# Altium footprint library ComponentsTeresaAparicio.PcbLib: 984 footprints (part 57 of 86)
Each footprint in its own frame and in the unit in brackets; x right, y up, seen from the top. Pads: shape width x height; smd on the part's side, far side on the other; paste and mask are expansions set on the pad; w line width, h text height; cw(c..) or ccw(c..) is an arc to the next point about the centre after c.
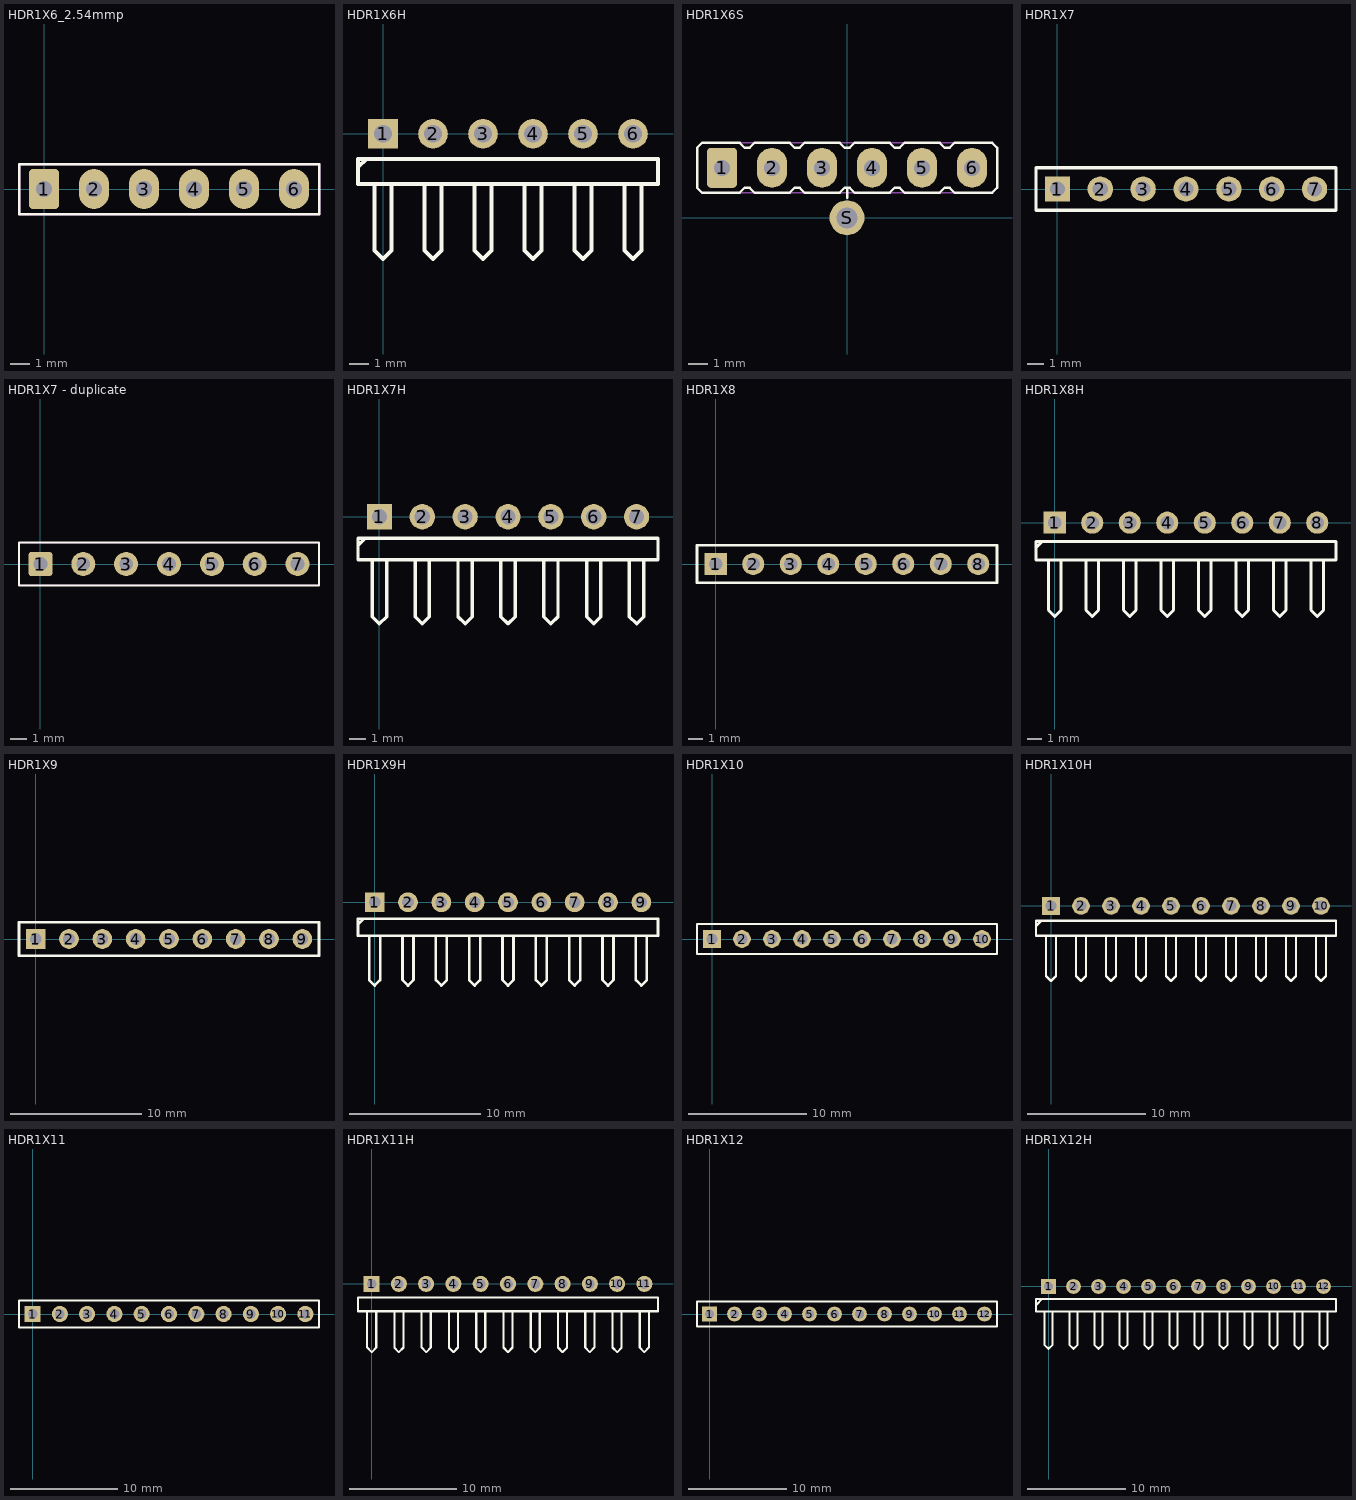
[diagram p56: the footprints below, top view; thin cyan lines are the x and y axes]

## HDR1X6_2.54mmp [mil] "Connector; Header; 6 Position 0.100\" pitch"
pads (6):
  rrect25% 60x80 hole 32: 1(0,0)
  oval 60x80 hole 32: 2(100,0) 3(200,0) 4(300,0) 5(400,0) 6(500,0)
Top Overlay:
  lines w5: -50,-50 -50,50 550,50 550,-50 -50,-50
Mechanical 13:
  lines w5: -50,-50 550,-50 550,50 -50,50 -50,-50

## HDR1X6H [mm] "Connector; Header; 6 Position; Right Angle"
pads (6):
  rect 1.5x1.5 hole 0.9: 1(0,0)
  round 1.5 hole 0.9: 2(2.54,0) 3(5.08,0) 4(7.62,0) 5(10.16,0) 6(12.7,0)
Top Overlay:
  lines w0.2: -1.27,-1.693 -0.847,-1.27 ; -0.423,-2.54 -0.423,-5.927 0,-6.35 0.423,-5.927 0.423,-2.54 ; 2.117,-2.54 2.117,-5.927 2.54,-6.35 2.963,-5.927 2.963,-2.54 ; 4.657,-2.54 4.657,-5.927 5.08,-6.35 5.503,-5.927 5.503,-2.54 ; 7.197,-2.54 7.197,-5.927 7.62,-6.35 8.043,-5.927 8.043,-2.54 ; 9.737,-2.54 9.737,-5.927 10.16,-6.35 10.583,-5.927 10.583,-2.54 ; 12.277,-2.54 12.277,-5.927 12.7,-6.35 13.123,-5.927 13.123,-2.54 ; -1.27,-2.54 -1.27,-1.27 13.97,-1.27 13.97,-2.54 -1.27,-2.54

## HDR1X6S [mil] "Connector; Special 6-position header with shield term"
pads (7):
  rrect25% 60x80 hole 32: 1(-250,100)
  oval 60x80 hole 32: 2(-150,100) 3(-50,100) 4(50,100) 5(150,100) 6(250,100)
  round 70 hole 42: S(0,0)
Top Overlay:
  lines w5: 0,40 0,60 ; -300,60 -300,140 -290,150 -215,150 -205,140 -195,140 -185,150 -115,150 -105,140 -95,140 -85,150 -15,150 -5,140 5,140 15,150 85,150 95,140 105,140 115,150 185,150 195,140 205,140 215,150 290,150 300,140 300,60 290,50 215,50 205,60 195,60 185,50 115,50 105,60 95,60 85,50 15,50 5,60 -5,60 -15,50 -85,50 -95,60 -105,60 -115,50 -185,50 -195,60 -205,60 -215,50 -290,50 -300,60
Mechanical 13:
  lines w3: -300,60 -290,50 290,50 300,60 300,140 290,150 -290,150 -300,140 -300,60

## HDR1X7 [mm] "Connector; Header; 7 Position"
pads (7):
  rect 1.5x1.5 hole 0.9: 1(0,0)
  round 1.5 hole 0.9: 2(2.54,0) 3(5.08,0) 4(7.62,0) 5(10.16,0) 6(12.7,0) 7(15.24,0)
Top Overlay:
  lines w0.2: -1.27,-1.27 -1.27,1.27 16.51,1.27 16.51,-1.27 -1.27,-1.27

## HDR1X7 - duplicate [mil] "Connector; Header; 7 Position"
pads (7):
  rrect25% 56x56 / inner rrect25% 56x56 / far side rrect25% 72x72 hole 32: 1(0,0)
  round 56 / inner round 56 / far side round 72 hole 32: 2(100,0) 3(200,0) 4(300,0) 5(400,0) 6(500,0) 7(600,0)
Top Overlay:
  lines w5: -50,-50 650,-50 650,50 -50,50 -50,-50
Mechanical 13:
  lines w3: -50,-50 -50,50 650,50 650,-50 -50,-50

## HDR1X7H [mm] "Connector; Header; 7 Position; Right Angle"
pads (7):
  rect 1.5x1.5 hole 0.9: 1(0,0)
  round 1.5 hole 0.9: 2(2.54,0) 3(5.08,0) 4(7.62,0) 5(10.16,0) 6(12.7,0) 7(15.24,0)
Top Overlay:
  lines w0.2: -1.27,-1.693 -0.847,-1.27 ; -0.423,-2.54 -0.423,-5.927 0,-6.35 0.423,-5.927 0.423,-2.54 ; 2.117,-2.54 2.117,-5.927 2.54,-6.35 2.963,-5.927 2.963,-2.54 ; 4.657,-2.54 4.657,-5.927 5.08,-6.35 5.503,-5.927 5.503,-2.54 ; 7.197,-2.54 7.197,-5.927 7.62,-6.35 8.043,-5.927 8.043,-2.54 ; 9.737,-2.54 9.737,-5.927 10.16,-6.35 10.583,-5.927 10.583,-2.54 ; 12.277,-2.54 12.277,-5.927 12.7,-6.35 13.123,-5.927 13.123,-2.54 ; 14.817,-2.54 14.817,-5.927 15.24,-6.35 15.663,-5.927 15.663,-2.54 ; -1.27,-2.54 -1.27,-1.27 16.51,-1.27 16.51,-2.54 -1.27,-2.54

## HDR1X8 [mm] "Connector; Header; 8 Position"
pads (8):
  rect 1.5x1.5 hole 0.9: 1(0,0)
  round 1.5 hole 0.9: 2(2.54,0) 3(5.08,0) 4(7.62,0) 5(10.16,0) 6(12.7,0) 7(15.24,0) 8(17.78,0)
Top Overlay:
  lines w0.2: -1.27,-1.27 19.05,-1.27 19.05,1.27 -1.27,1.27 -1.27,-1.27

## HDR1X8H [mm] "Connector; Header; 8 Position; Right Angle"
pads (8):
  rect 1.5x1.5 hole 0.9: 1(0,0)
  round 1.5 hole 0.9: 2(2.54,0) 3(5.08,0) 4(7.62,0) 5(10.16,0) 6(12.7,0) 7(15.24,0) 8(17.78,0)
Top Overlay:
  lines w0.2: -1.27,-1.693 -0.847,-1.27 ; -0.423,-2.54 -0.423,-5.927 0,-6.35 0.423,-5.927 0.423,-2.54 ; 2.117,-2.54 2.117,-5.927 2.54,-6.35 2.963,-5.927 2.963,-2.54 ; 4.657,-2.54 4.657,-5.927 5.08,-6.35 5.503,-5.927 5.503,-2.54 ; 7.197,-2.54 7.197,-5.927 7.62,-6.35 8.043,-5.927 8.043,-2.54 ; 9.737,-2.54 9.737,-5.927 10.16,-6.35 10.583,-5.927 10.583,-2.54 ; 12.277,-2.54 12.277,-5.927 12.7,-6.35 13.123,-5.927 13.123,-2.54 ; 14.817,-2.54 14.817,-5.927 15.24,-6.35 15.663,-5.927 15.663,-2.54 ; 17.357,-2.54 17.357,-5.927 17.78,-6.35 18.203,-5.927 18.203,-2.54 ; -1.27,-2.54 -1.27,-1.27 19.05,-1.27 19.05,-2.54 -1.27,-2.54

## HDR1X9 [mm] "Connector; Header; 9 Position"
pads (9):
  rect 1.5x1.5 hole 0.9: 1(0,0)
  round 1.5 hole 0.9: 2(2.54,0) 3(5.08,0) 4(7.62,0) 5(10.16,0) 6(12.7,0) 7(15.24,0) 8(17.78,0) 9(20.32,0)
Top Overlay:
  lines w0.2: -1.27,-1.27 -1.27,1.27 21.59,1.27 21.59,-1.27 -1.27,-1.27

## HDR1X9H [mm] "Connector; Header; 9 Position; Right Angle"
pads (9):
  rect 1.5x1.5 hole 0.9: 1(0,0)
  round 1.5 hole 0.9: 2(2.54,0) 3(5.08,0) 4(7.62,0) 5(10.16,0) 6(12.7,0) 7(15.24,0) 8(17.78,0) 9(20.32,0)
Top Overlay:
  lines w0.2: -1.27,-1.693 -0.847,-1.27 ; -0.423,-2.54 -0.423,-5.927 0,-6.35 0.423,-5.927 0.423,-2.54 ; 2.117,-2.54 2.117,-5.927 2.54,-6.35 2.963,-5.927 2.963,-2.54 ; 4.657,-2.54 4.657,-5.927 5.08,-6.35 5.503,-5.927 5.503,-2.54 ; 7.197,-2.54 7.197,-5.927 7.62,-6.35 8.043,-5.927 8.043,-2.54 ; 9.737,-2.54 9.737,-5.927 10.16,-6.35 10.583,-5.927 10.583,-2.54 ; 12.277,-2.54 12.277,-5.927 12.7,-6.35 13.123,-5.927 13.123,-2.54 ; 14.817,-2.54 14.817,-5.927 15.24,-6.35 15.663,-5.927 15.663,-2.54 ; 17.357,-2.54 17.357,-5.927 17.78,-6.35 18.203,-5.927 18.203,-2.54 ; 19.897,-2.54 19.897,-5.927 20.32,-6.35 20.743,-5.927 20.743,-2.54 ; -1.27,-2.54 21.59,-2.54 21.59,-1.27 -1.27,-1.27 -1.27,-2.54

## HDR1X10 [mm] "Connector; Header; 10 Position"
pads (10):
  rect 1.5x1.5 hole 0.9: 1(0,0)
  round 1.5 hole 0.9: 2(2.54,0) 3(5.08,0) 4(7.62,0) 5(10.16,0) 6(12.7,0) 7(15.24,0) 8(17.78,0) 9(20.32,0) 10(22.86,0)
Top Overlay:
  lines w0.2: -1.27,-1.27 24.13,-1.27 24.13,1.27 0.635,1.27 -1.27,1.27 -1.27,-1.27

## HDR1X10H [mm] "Connector; Header; 10 Position; Right Angle"
pads (10):
  rect 1.5x1.5 hole 0.9: 1(0,0)
  round 1.5 hole 0.9: 2(2.54,0) 3(5.08,0) 4(7.62,0) 5(10.16,0) 6(12.7,0) 7(15.24,0) 8(17.78,0) 9(20.32,0) 10(22.86,0)
Top Overlay:
  lines w0.2: -1.27,-1.693 -0.847,-1.27 ; -0.423,-2.54 -0.423,-5.927 0,-6.35 0.423,-5.927 0.423,-2.54 ; 2.117,-2.54 2.117,-5.927 2.54,-6.35 2.963,-5.927 2.963,-2.54 ; 4.657,-2.54 4.657,-5.927 5.08,-6.35 5.503,-5.927 5.503,-2.54 ; 7.197,-2.54 7.197,-5.927 7.62,-6.35 8.043,-5.927 8.043,-2.54 ; 9.737,-2.54 9.737,-5.927 10.16,-6.35 10.583,-5.927 10.583,-2.54 ; 12.277,-2.54 12.277,-5.927 12.7,-6.35 13.123,-5.927 13.123,-2.54 ; 14.817,-2.54 14.817,-5.927 15.24,-6.35 15.663,-5.927 15.663,-2.54 ; 17.357,-2.54 17.357,-5.927 17.78,-6.35 18.203,-5.927 18.203,-2.54 ; 19.897,-2.54 19.897,-5.927 20.32,-6.35 20.743,-5.927 20.743,-2.54 ; 22.437,-2.54 22.437,-5.927 22.86,-6.35 23.283,-5.927 23.283,-2.54 ; -1.27,-2.54 24.13,-2.54 24.13,-1.27 0.635,-1.27 -1.27,-1.27 -1.27,-2.54

## HDR1X11 [mm] "Connector; Header; 11 Position"
pads (11):
  rect 1.5x1.5 hole 0.9: 1(0,0)
  round 1.5 hole 0.9: 2(2.54,0) 3(5.08,0) 4(7.62,0) 5(10.16,0) 6(12.7,0) 7(15.24,0) 8(17.78,0) 9(20.32,0) 10(22.86,0) 11(25.4,0)
Top Overlay:
  lines w0.2: -1.27,-1.27 26.67,-1.27 26.67,1.27 0.635,1.27 -1.27,1.27 -1.27,-1.27

## HDR1X11H [mm] "Connector; Header; 11 Position; Right Angle"
pads (11):
  rect 1.5x1.5 hole 0.9: 1(0,0)
  round 1.5 hole 0.9: 2(2.54,0) 3(5.08,0) 4(7.62,0) 5(10.16,0) 6(12.7,0) 7(15.24,0) 8(17.78,0) 9(20.32,0) 10(22.86,0) 11(25.4,0)
Top Overlay:
  lines w0.2: -0.423,-2.54 -0.423,-5.927 0,-6.35 0.423,-5.927 0.423,-2.54 ; 2.117,-2.54 2.117,-5.927 2.54,-6.35 2.963,-5.927 2.963,-2.54 ; 4.657,-2.54 4.657,-5.927 5.08,-6.35 5.503,-5.927 5.503,-2.54 ; 7.197,-2.54 7.197,-5.927 7.62,-6.35 8.043,-5.927 8.043,-2.54 ; 9.737,-2.54 9.737,-5.927 10.16,-6.35 10.583,-5.927 10.583,-2.54 ; 12.277,-2.54 12.277,-5.927 12.7,-6.35 13.123,-5.927 13.123,-2.54 ; 14.817,-2.54 14.817,-5.927 15.24,-6.35 15.663,-5.927 15.663,-2.54 ; 17.357,-2.54 17.357,-5.927 17.78,-6.35 18.203,-5.927 18.203,-2.54 ; 19.897,-2.54 19.897,-5.927 20.32,-6.35 20.743,-5.927 20.743,-2.54 ; 22.437,-2.54 22.437,-5.927 22.86,-6.35 23.283,-5.927 23.283,-2.54 ; 24.977,-2.54 24.977,-5.927 25.4,-6.35 25.823,-5.927 25.823,-2.54 ; -1.27,-2.54 26.67,-2.54 26.67,-1.27 -1.27,-1.27 -1.27,-2.54

## HDR1X12 [mm] "Connector; Header; 12 Position"
pads (12):
  rect 1.5x1.5 hole 0.9: 1(0,0)
  round 1.5 hole 0.9: 2(2.54,0) 3(5.08,0) 4(7.62,0) 5(10.16,0) 6(12.7,0) 7(15.24,0) 8(17.78,0) 9(20.32,0) 10(22.86,0) 11(25.4,0) 12(27.94,0)
Top Overlay:
  lines w0.2: -1.27,-1.27 29.21,-1.27 29.21,1.27 0.635,1.27 -1.27,1.27 -1.27,-1.27

## HDR1X12H [mm] "Connector; Header; 12 Position; Right Angle"
pads (12):
  rect 1.5x1.5 hole 0.9: 1(0,0)
  round 1.5 hole 0.9: 2(2.54,0) 3(5.08,0) 4(7.62,0) 5(10.16,0) 6(12.7,0) 7(15.24,0) 8(17.78,0) 9(20.32,0) 10(22.86,0) 11(25.4,0) 12(27.94,0)
Top Overlay:
  lines w0.2: -1.27,-1.905 -0.635,-1.27 ; -0.423,-2.54 -0.423,-5.927 0,-6.35 0.423,-5.927 0.423,-2.54 ; 2.117,-2.54 2.117,-5.927 2.54,-6.35 2.963,-5.927 2.963,-2.54 ; 4.657,-2.54 4.657,-5.927 5.08,-6.35 5.503,-5.927 5.503,-2.54 ; 7.197,-2.54 7.197,-5.927 7.62,-6.35 8.043,-5.927 8.043,-2.54 ; 9.737,-2.54 9.737,-5.927 10.16,-6.35 10.583,-5.927 10.583,-2.54 ; 12.277,-2.54 12.277,-5.927 12.7,-6.35 13.123,-5.927 13.123,-2.54 ; 14.817,-2.54 14.817,-5.927 15.24,-6.35 15.663,-5.927 15.663,-2.54 ; 17.357,-2.54 17.357,-5.927 17.78,-6.35 18.203,-5.927 18.203,-2.54 ; 19.897,-2.54 19.897,-5.927 20.32,-6.35 20.743,-5.927 20.743,-2.54 ; 22.437,-2.54 22.437,-5.927 22.86,-6.35 23.283,-5.927 23.283,-2.54 ; 24.977,-2.54 24.977,-5.927 25.4,-6.35 25.823,-5.927 25.823,-2.54 ; 27.517,-2.54 27.517,-5.927 27.94,-6.35 28.363,-5.927 28.363,-2.54 ; -1.27,-2.54 -1.27,-1.27 0.635,-1.27 29.21,-1.27 29.21,-2.54 -1.27,-2.54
